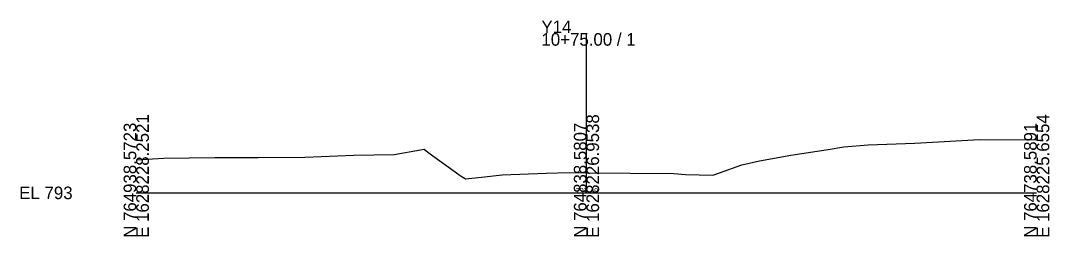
# Model space of a CAD drawing. Extents: x -26 to 1403, y -10 to 4517.
# Drawn here: x -25.7 to 202.8, y 1490.3 to 1538.3 of the extents above; entities that cross this region are included whole.
import ezdxf

# ---------------------------------------------------------------- set-up
doc = ezdxf.new("R2010")
doc.units = 0
for name, color, linetype in [('Default', 7, 'Continuous'), ('Exist CMT Pavement', 7, 'Continuous'), ('Exist Cross Section Cell', 7, 'Continuous'), ('Exist XS Center Line Elevation Label', 7, 'Continuous'), ('Exist XS Ground Line', 7, 'Continuous')]:
    doc.layers.add(name, color=color, linetype=linetype)

msp = doc.modelspace()

# ---------------------------------------------------------------- linework, layer by layer
at = {"layer": 'Exist CMT Pavement'}
msp.add_lwpolyline([(100, 1504.49), (119.43, 1504.29)], dxfattribs=at)
at = {"layer": 'Exist Cross Section Cell'}
for p, q in [((100, 1500), (100, 1535.53)), ((0, 1500), (100, 1500)), ((100, 1500), (200, 1500))]:
    msp.add_line(p, q, dxfattribs=at)
at = {"layer": 'Exist XS Ground Line'}
msp.add_lwpolyline([(0, 1507.37), (6.06, 1507.73), (17.47, 1507.9), (27.1, 1507.84), (37.47, 1507.97), (48.35, 1508.42), (57.26, 1508.52), (63.14, 1509.6), (63.94, 1509.7), (64.74, 1509.07), (71.92, 1503.89), (73.13, 1503.09), (76.67, 1503.47), (81.25, 1503.99), (91.02, 1504.35), (96.16, 1504.53), (100, 1504.49), (119.43, 1504.29), (122.02, 1504.09), (128.1, 1503.92), (129.56, 1504.43), (134.5, 1506.22), (138.42, 1507.1), (145.41, 1508.35), (153.67, 1509.66), (157.14, 1510.21), (162.58, 1510.68), (172.93, 1511.06), (187.28, 1511.84), (200, 1511.82)], dxfattribs=at)

# ---------------------------------------------------------------- texts
at = {"layer": 'Default'}
msp.add_text('-', height=0.0001, dxfattribs=at).set_placement((0, 1500))
at = {"layer": 'Exist Cross Section Cell'}
for s, p in [('Y14', (90, 1535.53)), ('10+75.00 / 1', (90, 1532.73)), ('EL 793', (-26, 1498.6))]:
    msp.add_text(s, height=2.8, dxfattribs=at).set_placement(p)
for s, p in [('N 764938.5723', (0, 1490)), ('E 1628228.2521', (2.8, 1490)), ('N 764838.5807', (100, 1490)), ('E 1628226.9538', (102.8, 1490)), ('N 764738.5891', (200, 1490)), ('E 1628225.6554', (202.8, 1490))]:
    msp.add_text(s, height=2.8, rotation=90, dxfattribs=at).set_placement(p)
at = {"layer": 'Exist XS Center Line Elevation Label'}
msp.add_text('797.49', height=1.2, dxfattribs=at).set_placement((97.56, 1499.89))

doc.saveas('drawing.dxf')
